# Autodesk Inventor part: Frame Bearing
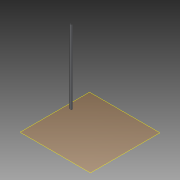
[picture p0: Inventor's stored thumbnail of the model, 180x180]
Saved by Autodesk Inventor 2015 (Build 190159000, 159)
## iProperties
Created: 2015-04
Part Number: Frame Bearing
Material: Generic
Document SubType Name: Modeling
Designer: suporte
Density: 1 g/cm^3
Appearance: Default
Author: suporte
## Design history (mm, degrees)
workplane "Work Plane1"
sketch "Sketch1"
  geometry: L1 (-859.783, 290)-(-840.217, 290) reference; L2 (-825, 295)-(-875, 295); L3 (-875, 295)-(-875, 330); L4 (-825, 295)-(-825, 330); L5 (-825, 330)-(-825.6, 330); L6 (-825.6, 330)-(-825.6, 295.6); L7 (-825.6, 295.6)-(-874.4, 295.6); L8 (-874.4, 295.6)-(-874.4, 330); L9 (-874.4, 330)-(-875, 330); 4 further points
  constraints: 16 end point, 6 perpendicular, 3 midpoint, 2 vertical alignment, 1 horizontal, 1 point on line, 1 vertical
  dimensions: "d0" = 50 distance of L2.start L2.end; "d1" = 5 distance between parallel lines of L1 L2; "d2" = 35 distance of L2.start L4.end; "d3" = 0.6 distance between parallel lines of L4 L6; "d4" = 0.6 distance between parallel lines of L2 L7
extrude "Extrusion1" new body sketch "Sketch1" distance "d5" = 2100; taper "d6" = 0 deg
body "Solid1"
node "Reference1"
